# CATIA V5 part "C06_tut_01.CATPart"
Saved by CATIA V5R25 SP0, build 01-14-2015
Part number: Part1
Bounding box of the stored display mesh (mm): x -101.061 to 0, y -66 to 77.28, z -14 to 91.937
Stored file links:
  E:\ashutosh\Academics\Catia\CATIA V5-6R2013_partfiles\Tutorials_ver_2\C06_tut_01.CATPart
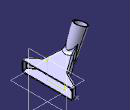
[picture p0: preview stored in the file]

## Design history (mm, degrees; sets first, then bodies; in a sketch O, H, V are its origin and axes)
Body1 (main body)
  Sketch1 on zx-plane, origin (0, 0, 0), H (-1, 0, 0), V (0, 0, 1)
    line L1 (0, 0) -> (61.837, 30.1599)
    line L2 (61.837, 30.1599) -> (86.4446, 85.4294)
    point P2 (86.4446, 85.4294)
    angle L1 H = 26
    angle L2 L1 = 140
    length L2 = 60.5
    length L1 = 68.8
  Sketch2 on yz-plane, origin (0, 0, 0), H (0, 1, 0), V (0, 0, 1)
    point P1 (77.2798, 0)
    coincidence: P1 H
  Plane1: type 3Points, Element1 Sketch1.O, Element2 vertex [element of Sketch1 | element of Sketch1], Element3 Sketch2
  Sketch3 on Plane1, origin (0, 0, 0), H (0, -1, 0), V (-0.8988, 0, 0.4384)
    point P1 (-66, 0)
    line L1 (-66, 0) -> (66, 0)
    point P2 (66, 0)
    line L2 (66, 0) -> (65.4759, 10)
    point P3 (65.4759, 10)
    line L3 (65.4759, 10) -> (33, 25)
    point P4 (33, 25)
    line L4 (33, 25) -> (12.1773, 65)
    point P5 (12.1773, 65)
    line L5 (12.1773, 65) -> (0, 65)
    point P6 (0, 65)
    reference intersected line E1 through (0, 0) direction (0, -1) from zx-plane
    axis line L6 (66, 0) -> (66, 116.8592)
    reference intersected line E2 through (0, 0) direction (0, -1) from zx-plane
    point P10 (0, 0)
    construction line L7 through (0, 0) direction (-1, 0)
    construction line L8 through (0, 0) direction (0, 1)
    point P11 (-66, 0)
    point P12 (-65.4759, 10)
    point P13 (-33, 25)
    point P14 (-12.1773, 65)
    point P15 (0, 65)
    line L9 (-66, 0) -> (-65.4759, 10)
    line L10 (-65.4759, 10) -> (-33, 25)
    line L11 (-33, 25) -> (-12.1773, 65)
    line L12 (-12.1773, 65) -> (0, 65)
    length L1 = 132
    distance P3 P2 V = 10
    distance L5 L1 = 65
    angle L2 L6 = 3
    distance P4 L1 = 25
    distance P4 V = 33
    angle L4 L11 = 55
    coincidence: P1 H, P6 V, P1 P11, P6 P15
    horizontal: L1 H, L5 H
    symmetry: P1 P2 E1, O P10 E2, H L7 E2, V L8 E2, P2 P11 E2, P3 P12 E2, P4 P13 E2, P5 P14 E2, P6 P15 E2, L2 L9 E2, L3 L10 E2, L4 L11 E2, L5 L12 E2
    vertical: L6 V
  Pad1: profile Sketch3, direction along xy-plane reversed, length 14, mirrored extent
  Plane2: type Normal, Curve Sketch1, RefPoint Sketch1.P2, Ratio 0
  Sketch4 on Plane2, origin (-46.0442, 0, 103.4169), H (0, -1, 0), V (0.9135, 0, 0.4067)
    circle A1 centre (0, -44.2238) radius 16
    point P1 (0, -44.2238)
    reference projected point E1 (0, -44.2238) from Sketch1.P2
    radius A1 = 16
    coincidence: P1 V, P1 E1
  Pad2: profile Sketch4, direction (-0.4067, 0, 0.9135), length 0, opposite side up to xy-plane
  Draft1: Angle -2, Neutral end face of Pad2, PullDir end face of Pad2, SupportToDraft face of Pad2 from Sketch4.A1
  Sketch5 on end face of Pad1, origin (-5.5161, 0, -11.3096), H (0, -1, 0), V (-0.8988, 0, 0.4384)
    point P1 (0, 51.4346)
    line L1 (22.6679, 95.8293) -> (22.6679, 7.0398)
    line L2 (22.6679, 7.0398) -> (-22.6679, 7.0398)
    line L3 (-22.6679, 7.0398) -> (-22.6679, 95.8293)
    line L4 (-22.6679, 95.8293) -> (22.6679, 95.8293)
    coincidence: P1 V
    vertical: L1 V, L3 V
    horizontal: L2 H, L4 H
    equidistance: L1 L3 P1, L2 L4 P1
  Pocket1: profile Sketch5, direction (-0.4384, 0, -0.8988), length 20
  Fillet1: radius 12, on edge [face of Pad2 from Sketch4.A1 | start face of Pad1]; edge [face of Pad2 from Sketch4.A1 | face of Pad1 from Sketch3.L11]; edge [face of Pad2 from Sketch4.A1 | face of Pad1 from Sketch3.L4]
  Fillet2: radius 3, on edge [start face of Pad1 | face of Pad1 from Sketch3.L4]; edge [start face of Pad1 | face of Pad1 from Sketch3.L11]; edge [start face of Pad1 | face of Pad1 from Sketch3.L3]; edge [start face of Pad1 | face of Pad1 from Sketch3.L2]; edge [start face of Pad1 | face of Pad1 from Sketch3.L9]; edge [face of Pad1 from Sketch3.L9 | face of Pocket1]; edge [face of Pad1 from Sketch3.L9 | face of Pad1 from Sketch3.L10]; edge [start face of Pad1 | face of Pad1 from Sketch3.L10]; edge [face of Pad1 from Sketch3.L2 | face of Pocket1]; edge [face of Pad1 from Sketch3.L10 | face of Pad1 from Sketch3.L11]; edge [face of Pad1 from Sketch3.L4 | face of Pad1 from Sketch3.L3]; edge [face of Pad1 from Sketch3.L3 | face of Pocket1]; edge [face of Pocket1 | face of Pad1 from Sketch3.L4]; edge [face of Pad1 from Sketch3.L11 | face of Pocket1]; edge [face of Pad1 from Sketch3.L10 | face of Pocket1]; edge [face of Pad1 from Sketch3.L3 | face of Pad1 from Sketch3.L2]
  Shell1: ExtOffset 0, Face (end face of Pad2; face of Pad1 from Sketch3.L1), IntOffset 2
